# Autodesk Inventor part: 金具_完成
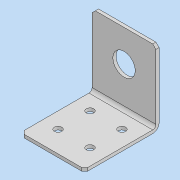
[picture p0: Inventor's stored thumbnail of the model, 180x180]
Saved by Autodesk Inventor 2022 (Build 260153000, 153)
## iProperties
Created: 2021-07
Part Number: 金具_完成
Material: 一般
Document SubType Name: Modeling
Designer: DesignLab
Density: 1 g/cm^3
Appearance: 既定
Author: DesignLab
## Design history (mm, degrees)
sketch "スケッチ1"
  geometry: L1 (0, 0)-(70, 0); L2 (70, 0)-(70, 70); L3 (70, 70)-(0, 70); L4 (0, 70)-(0, 0)
  constraints: 8 end point, 2 parallel, 1 horizontal, 1 perpendicular
  dimensions: "d0" = 70 distance of L3.end L2.end; "d1" = 70 distance of L2.end L1.end
extrude "押し出し1" new body sketch "スケッチ1" taper "d3" = 0 deg; stored distance "全幅" = 60
fillet "フィレット1" dims "d4" = 6
feature "シェル1" dims "d5" = 3
sketch "スケッチ2"
  geometry: L1 (0, -6)-(60, -6) reference; 3 further points
  constraints: 1 midpoint, 1 vertical alignment
  dimensions: "d6" = 40 distance from line of point (30, 34) L1
hole "穴1" sketch "スケッチ2" at (30, 34) diameter "d7" = 21; stored, may be unused: countersink angle "d11" = 90 deg, drill point angle "d13" = 118 deg; dims "d8" = 6, "d9" = 4, "d10" = 2, "d12" = 8
sketch "スケッチ3"
  geometry: L1 (15, -44)-(45, -44); L2 (45, -44)-(45, -14); L3 (45, -14)-(15, -14); L4 (15, -14)-(15, -44); L5 (15, -44)-(45, -14); L6 (45, -44)-(15, -14); L7 (60, 6)-(0, 6) reference; 4 further points
  constraints: 12 end point, 4 midpoint, 2 parallel, 1 horizontal, 1 perpendicular, 1 vertical alignment
  dimensions: "d14" = 30 distance of L3.end L2.end (= 0.5 x 全幅); "d15" = 30 distance of L2.end L1.end; "d16" = 20 distance between parallel lines of L3 L7
hole "穴2" sketch "スケッチ3" at (15, -44), (45, -44), (15, -14), (45, -14) diameter "d17" = 7; stored, may be unused: countersink angle "d21" = 90 deg, drill point angle "d23" = 118 deg; dims "d18" = 6, "d19" = 4, "d20" = 2, "d22" = 8
chamfer "面取り1" distance "d24" = 3; stored, may be unused: second distance "d25" = 2, angle "d26" = 45 deg
node "ソリッド1"
